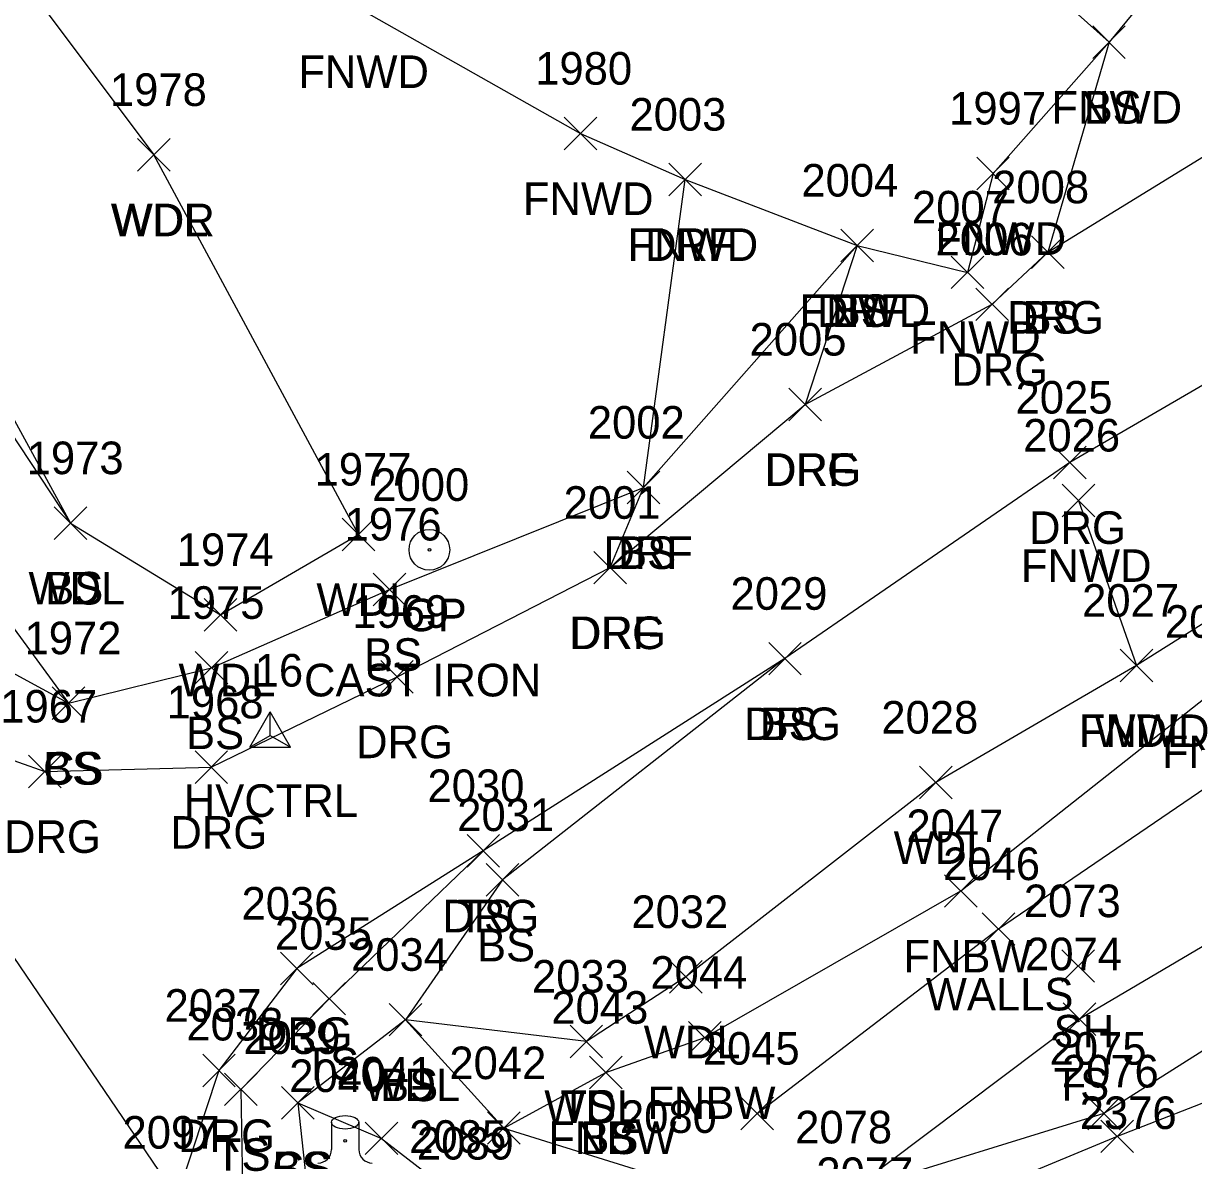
# Model space of a CAD drawing. Extents: x 1501299 to 1502485, y 381423 to 383765.
# Drawn here: x 1501597.6 to 1501669.5, y 383335.7 to 383405.5 of the extents above; entities that cross this region are included whole.
import ezdxf

# ---------------------------------------------------------------- set-up
doc = ezdxf.new("R2010")
doc.units = 0
for name, color, linetype in [('C_A', 7, 'Continuous'), ('C_I', 7, 'Continuous'), ('CPSM', 7, 'Continuous'), ('L_A', 7, 'Continuous'), ('L_I', 7, 'Continuous'), ('L_TIC', 7, 'Continuous'), ('LAWA', 7, 'Continuous'), ('LAWE', 7, 'Continuous'), ('LELB', 7, 'Continuous'), ('LFNC', 7, 'Continuous'), ('LTS', 7, 'Continuous'), ('LWS', 7, 'Continuous'), ('M_I', 7, 'Continuous'), ('P_I', 7, 'Continuous'), ('PET', 7, 'Continuous'), ('R_A', 7, 'Continuous'), ('R_C', 7, 'Continuous'), ('R_I', 7, 'Continuous'), ('R_TIC', 7, 'Continuous'), ('RDF', 7, 'Continuous'), ('RDG', 7, 'Continuous'), ('RGP', 7, 'Continuous')]:
    doc.layers.add(name, color=color, linetype=linetype)

msp = doc.modelspace()

# ---------------------------------------------------------------- linework, layer by layer
at = {"layer": 'CPSM'}
for p, q in [((1501611.52, 383361.059), (1501612.77, 383363.224)), ((1501614.02, 383361.059), (1501612.77, 383363.224)), ((1501612.771, 383361.781), (1501612.77, 383363.224)), ((1501611.52, 383361.059), (1501612.771, 383361.781)), ((1501612.771, 383361.781), (1501612.771, 383361.781)), ((1501612.771, 383361.781), (1501614.02, 383361.059)), ((1501611.52, 383361.059), (1501614.02, 383361.059))]:
    msp.add_line(p, q, dxfattribs=at)
at = {"layer": 'L_TIC'}
for points in [[(1501663.269, 383403.339), (1501665.269, 383405.339)], [(1501665.269, 383403.339), (1501663.269, 383405.339)], [(1501663.269, 383403.339), (1501665.269, 383405.339)], [(1501665.269, 383403.339), (1501663.269, 383405.339)], [(1501630.819, 383397.728), (1501632.819, 383399.728)], [(1501632.819, 383397.728), (1501630.819, 383399.728)], [(1501604.623, 383396.423), (1501606.623, 383398.423)], [(1501606.623, 383396.423), (1501604.623, 383398.423)], [(1501604.623, 383396.423), (1501606.623, 383398.423)], [(1501606.623, 383396.423), (1501604.623, 383398.423)], [(1501656.147, 383395.281), (1501658.147, 383397.281)], [(1501658.147, 383395.281), (1501656.147, 383397.281)], [(1501637.245, 383394.907), (1501639.245, 383396.907)], [(1501639.245, 383394.907), (1501637.245, 383396.907)], [(1501647.802, 383390.857), (1501649.802, 383392.857)], [(1501649.802, 383390.857), (1501647.802, 383392.857)], [(1501647.802, 383390.857), (1501649.802, 383392.857)], [(1501649.802, 383390.857), (1501647.802, 383392.857)], [(1501659.515, 383390.446), (1501661.515, 383392.446)], [(1501661.515, 383390.446), (1501659.515, 383392.446)], [(1501654.586, 383389.206), (1501656.586, 383391.206)], [(1501656.586, 383389.206), (1501654.586, 383391.206)], [(1501654.586, 383389.206), (1501656.586, 383391.206)], [(1501656.586, 383389.206), (1501654.586, 383391.206)], [(1501634.688, 383376), (1501636.688, 383378)], [(1501636.688, 383376), (1501634.688, 383378)], [(1501661.392, 383375.208), (1501663.392, 383377.208)], [(1501663.392, 383375.208), (1501661.392, 383377.208)], [(1501599.513, 383373.819), (1501601.513, 383375.819)], [(1501601.513, 383373.819), (1501599.513, 383375.819)], [(1501599.513, 383373.819), (1501601.513, 383375.819)], [(1501601.513, 383373.819), (1501599.513, 383375.819)], [(1501617.19, 383373.119), (1501619.19, 383375.119)], [(1501619.19, 383373.119), (1501617.19, 383375.119)], [(1501619.094, 383369.747), (1501621.094, 383371.747)], [(1501621.094, 383369.747), (1501619.094, 383371.747)], [(1501608.724, 383368.181), (1501610.724, 383370.181)], [(1501610.724, 383368.181), (1501608.724, 383370.181)], [(1501643.375, 383365.495), (1501645.375, 383367.495)], [(1501645.375, 383365.495), (1501643.375, 383367.495)], [(1501664.955, 383365.069), (1501666.955, 383367.069)], [(1501666.955, 383365.069), (1501664.955, 383367.069)], [(1501664.955, 383365.069), (1501666.955, 383367.069)], [(1501666.955, 383365.069), (1501664.955, 383367.069)], [(1501608.161, 383364.939), (1501610.161, 383366.939)], [(1501610.161, 383364.939), (1501608.161, 383366.939)], [(1501599.381, 383362.765), (1501601.381, 383364.765)], [(1501601.381, 383362.765), (1501599.381, 383364.765)], [(1501599.381, 383362.765), (1501601.381, 383364.765)], [(1501601.381, 383362.765), (1501599.381, 383364.765)], [(1501652.629, 383357.895), (1501654.629, 383359.895)], [(1501654.629, 383357.895), (1501652.629, 383359.895)], [(1501624.853, 383353.693), (1501626.853, 383355.693)], [(1501626.853, 383353.693), (1501624.853, 383355.693)], [(1501626.025, 383351.911), (1501628.025, 383353.911)], [(1501628.025, 383351.911), (1501626.025, 383353.911)], [(1501654.168, 383351.235), (1501656.168, 383353.235)], [(1501656.168, 383351.235), (1501654.168, 383353.235)], [(1501656.478, 383348.901), (1501658.478, 383350.901)], [(1501658.478, 383348.901), (1501656.478, 383350.901)], [(1501661.379, 383346.627), (1501663.379, 383348.627)], [(1501663.379, 383346.627), (1501661.379, 383348.627)], [(1501637.285, 383345.961), (1501639.285, 383347.961)], [(1501639.285, 383345.961), (1501637.285, 383347.961)], [(1501615.397, 383344.622), (1501617.397, 383346.622)], [(1501617.397, 383344.622), (1501615.397, 383346.622)], [(1501620.074, 383343.333), (1501622.074, 383345.333)], [(1501622.074, 383343.333), (1501620.074, 383345.333)], [(1501620.074, 383343.333), (1501622.074, 383345.333)], [(1501622.074, 383343.333), (1501620.074, 383345.333)], [(1501661.456, 383343.366), (1501663.456, 383345.366)], [(1501663.456, 383343.366), (1501661.456, 383345.366)], [(1501638.45, 383342.232), (1501640.45, 383344.232)], [(1501640.45, 383342.232), (1501638.45, 383344.232)], [(1501631.179, 383341.995), (1501633.179, 383343.995)], [(1501633.179, 383341.995), (1501631.179, 383343.995)], [(1501631.179, 383341.995), (1501633.179, 383343.995)], [(1501633.179, 383341.995), (1501631.179, 383343.995)], [(1501632.369, 383340.084), (1501634.369, 383342.084)], [(1501634.369, 383340.084), (1501632.369, 383342.084)], [(1501632.369, 383340.084), (1501634.369, 383342.084)], [(1501634.369, 383340.084), (1501632.369, 383342.084)], [(1501609.965, 383339.056), (1501611.965, 383341.056)], [(1501611.965, 383339.056), (1501609.965, 383341.056)], [(1501613.47, 383338.228), (1501615.47, 383340.228)], [(1501615.47, 383338.228), (1501613.47, 383340.228)], [(1501613.47, 383338.228), (1501615.47, 383340.228)], [(1501615.47, 383338.228), (1501613.47, 383340.228)], [(1501641.667, 383337.571), (1501643.667, 383339.571)], [(1501643.667, 383337.571), (1501641.667, 383339.571)], [(1501662.959, 383337.57), (1501664.959, 383339.57)], [(1501664.959, 383337.57), (1501662.959, 383339.57)], [(1501626.11, 383336.683), (1501628.11, 383338.683)], [(1501628.11, 383336.683), (1501626.11, 383338.683)], [(1501626.11, 383336.683), (1501628.11, 383338.683)], [(1501628.11, 383336.683), (1501626.11, 383338.683)], [(1501618.607, 383336.048), (1501620.607, 383338.048)], [(1501620.607, 383336.048), (1501618.607, 383338.048)], [(1501663.765, 383336.172), (1501665.765, 383338.172)], [(1501665.765, 383336.172), (1501663.765, 383338.172)]]:
    msp.add_lwpolyline(points, dxfattribs=at)
at = {"layer": 'LAWA'}
for points in [[(1501557.451, 383442.581), (1501575.149, 383424.231), (1501579.771, 383412.785), (1501600.513, 383374.819), (1501609.724, 383369.181), (1501618.19, 383374.119), (1501605.623, 383397.423)], [(1501557.451, 383442.581), (1501587.949, 383421), (1501605.623, 383397.423)], [(1501740.143, 383404.354), (1501720.425, 383392.48), (1501699.763, 383382.767), (1501677.935, 383373.609), (1501665.955, 383366.069), (1501653.629, 383358.895), (1501638.285, 383346.961), (1501632.179, 383342.995), (1501621.074, 383344.333), (1501627.11, 383337.683), (1501637.668, 383334.383)], [(1501750.74, 383385.706), (1501735.534, 383378.38), (1501721.306, 383366.598), (1501707.543, 383358.247), (1501693.275, 383349.984), (1501675.651, 383345.973), (1501663.959, 383338.57), (1501648.341, 383333.739), (1501637.668, 383334.383)]]:
    msp.add_lwpolyline(points, dxfattribs=at)
at = {"layer": 'LAWE'}
msp.add_lwpolyline([(1501751.7, 383384.782), (1501736.295, 383377.69), (1501721.533, 383363.11), (1501708.276, 383357.65), (1501696.432, 383349.133), (1501679.062, 383342.719), (1501664.765, 383337.172), (1501649.638, 383330.877), (1501644.08, 383325.549), (1501629.198, 383322.948), (1501623.396, 383326.029)], dxfattribs=at)
at = {"layer": 'LELB'}
for points in [[(1501358.62, 383732.982), (1501381.143, 383696.09), (1501398.686, 383667.715), (1501415.463, 383640.286), (1501435.304, 383603.989), (1501464.895, 383561.231), (1501485.321, 383525.1), (1501505.057, 383497.042), (1501522.935, 383468.146), (1501546.418, 383435.546), (1501564.602, 383407.152), (1501589.271, 383369.799), (1501600.381, 383363.765)], [(1501679.96, 383481.538), (1501668.05, 383454.246), (1501642.937, 383434.782), (1501647.006, 383419.763), (1501664.269, 383404.339), (1501660.515, 383391.446)], [(1501555.063, 383441.425), (1501575.01, 383413.454), (1501600.513, 383374.819)], [(1501550.473, 383437.331), (1501569.88, 383410.608), (1501593.858, 383372.658), (1501600.381, 383363.765), (1501609.161, 383365.939), (1501620.094, 383370.747), (1501635.688, 383377), (1501648.802, 383391.857)], [(1501644.375, 383366.495), (1501627.025, 383352.911), (1501621.074, 383344.333), (1501614.47, 383339.228), (1501619.607, 383337.048), (1501624.643, 383333.16)], [(1501704.558, 383362.823), (1501685.003, 383358.821), (1501674.317, 383351.353), (1501662.456, 383344.366), (1501648.341, 383333.739), (1501644.08, 383325.549)], [(1501625.853, 383354.693), (1501616.397, 383345.622), (1501610.965, 383340.056), (1501611.136, 383330.56), (1501615.516, 383325.125), (1501618.696, 383319.793)], [(1501627.11, 383337.683), (1501633.369, 383341.084)], [(1501614.47, 383339.228), (1501615.583, 383328.811), (1501620.097, 383323.129)]]:
    msp.add_lwpolyline(points, dxfattribs=at)
at = {"layer": 'LFNC'}
for points in [[(1501598.419, 383526.967), (1501583.574, 383507.223), (1501582.321, 383503.521), (1501551.423, 383461.963), (1501556.785, 383457.152), (1501570.079, 383443.827), (1501579.662, 383434.509), (1501590.927, 383422.471), (1501618.032, 383406.524), (1501631.819, 383398.728), (1501638.245, 383395.907), (1501648.802, 383391.857), (1501655.586, 383390.206)], [(1501703.45, 383452.334), (1501689.591, 383435.314), (1501672.608, 383414.438), (1501664.269, 383404.339), (1501657.147, 383396.281), (1501655.586, 383390.206)], [(1501662.392, 383376.208), (1501665.955, 383366.069)], [(1501633.369, 383341.084), (1501639.45, 383343.232), (1501655.168, 383352.235), (1501671.047, 383364.777), (1501683.649, 383372.385)]]:
    msp.add_lwpolyline(points, dxfattribs=at)
at = {"layer": 'LTS'}
for p, q in [((1501616.539, 383338.033), (1501616.539, 383336.366)), ((1501618.205, 383337.866), (1501618.205, 383338.033)), ((1501618.205, 383338.033), (1501618.205, 383336.366)), ((1501617.372, 383336.891), (1501617.372, 383336.891)), ((1501617.372, 383336.891), (1501617.372, 383336.891)), ((1501617.372, 383336.866), (1501617.372, 383336.866))]:
    msp.add_line(p, q, dxfattribs=at)
msp.add_circle((1501617.372, 383336.891), 0.0833, dxfattribs=at)
for centre, start, end in [((1501615.705, 383336.366), 270, 360), ((1501619.039, 383336.366), 180, 270)]:
    msp.add_arc(centre, 0.833, start, end, dxfattribs=at)
msp.add_ellipse((1501617.372, 383338.033), major_axis=(-0.833, 0), ratio=0.5, dxfattribs=at)
at = {"layer": 'LWS'}
msp.add_lwpolyline([(1501642.667, 383338.571), (1501657.478, 383349.901), (1501674.332, 383361.387), (1501682.14, 383365.291), (1501702.312, 383377.097)], dxfattribs=at)
at = {"layer": 'PET'}
msp.add_lwpolyline([(1501352.609, 383730.103), (1501376.04, 383692.663), (1501392.886, 383664.453), (1501409.551, 383637.048), (1501431.218, 383601.012), (1501459.286, 383556.771), (1501480.727, 383522.39), (1501500.041, 383493.106), (1501518.668, 383465.088), (1501539.809, 383433.288), (1501559.66, 383403.845), (1501585.888, 383364.546), (1501607.043, 383333.417), (1501616.485, 383318.818), (1501608.79, 383312.411), (1501601.645, 383306.284)], dxfattribs=at)
at = {"layer": 'R_TIC'}
for points in [[(1501637.245, 383394.907), (1501639.245, 383396.907)], [(1501639.245, 383394.907), (1501637.245, 383396.907)], [(1501647.802, 383390.857), (1501649.802, 383392.857)], [(1501649.802, 383390.857), (1501647.802, 383392.857)], [(1501659.515, 383390.446), (1501661.515, 383392.446)], [(1501661.515, 383390.446), (1501659.515, 383392.446)], [(1501656.095, 383387.246), (1501658.095, 383389.246)], [(1501658.095, 383387.246), (1501656.095, 383389.246)], [(1501644.617, 383381.098), (1501646.617, 383383.098)], [(1501646.617, 383381.098), (1501644.617, 383383.098)], [(1501644.617, 383381.098), (1501646.617, 383383.098)], [(1501646.617, 383381.098), (1501644.617, 383383.098)], [(1501660.87, 383377.539), (1501662.87, 383379.539)], [(1501662.87, 383377.539), (1501660.87, 383379.539)], [(1501634.688, 383376), (1501636.688, 383378)], [(1501636.688, 383376), (1501634.688, 383378)], [(1501632.637, 383371.08), (1501634.637, 383373.08)], [(1501634.637, 383371.08), (1501632.637, 383373.08)], [(1501632.637, 383371.08), (1501634.637, 383373.08)], [(1501634.637, 383371.08), (1501632.637, 383373.08)], [(1501643.375, 383365.495), (1501645.375, 383367.495)], [(1501645.375, 383365.495), (1501643.375, 383367.495)], [(1501619.557, 383364.386), (1501621.557, 383366.386)], [(1501621.557, 383364.386), (1501619.557, 383366.386)], [(1501597.939, 383358.572), (1501599.939, 383360.572)], [(1501599.939, 383358.572), (1501597.939, 383360.572)], [(1501608.156, 383358.828), (1501610.156, 383360.828)], [(1501610.156, 383358.828), (1501608.156, 383360.828)], [(1501624.853, 383353.693), (1501626.853, 383355.693)], [(1501626.853, 383353.693), (1501624.853, 383355.693)], [(1501613.404, 383346.477), (1501615.404, 383348.477)], [(1501615.404, 383346.477), (1501613.404, 383348.477)], [(1501608.625, 383340.209), (1501610.625, 383342.209)], [(1501610.625, 383340.209), (1501608.625, 383342.209)]]:
    msp.add_lwpolyline(points, dxfattribs=at)
at = {"layer": 'RDF'}
for points in [[(1501633.637, 383372.08), (1501635.688, 383377), (1501638.245, 383395.907)], [(1501648.802, 383391.857), (1501645.617, 383382.098)]]:
    msp.add_lwpolyline(points, dxfattribs=at)
at = {"layer": 'RDG'}
for points in [[(1501585.888, 383364.546), (1501592.449, 383361.853), (1501598.939, 383359.572), (1501609.156, 383359.828), (1501620.557, 383365.386), (1501633.637, 383372.08), (1501645.617, 383382.098), (1501657.095, 383388.246), (1501660.515, 383391.446), (1501681.22, 383404.169), (1501705.776, 383415.265), (1501726.712, 383424.327)], [(1501733.479, 383413.356), (1501709.016, 383404.067), (1501690.807, 383395.363), (1501661.87, 383378.539), (1501644.375, 383366.495), (1501625.853, 383354.693), (1501614.404, 383347.477), (1501609.625, 383341.209), (1501607.043, 383333.417)]]:
    msp.add_lwpolyline(points, dxfattribs=at)
at = {"layer": 'RGP'}
msp.add_line((1501622.543, 383373.177), (1501622.543, 383373.177), dxfattribs=at)
for radius in [1.25, 0.0833]:
    msp.add_circle((1501622.543, 383373.177), radius, dxfattribs=at)

# ---------------------------------------------------------------- texts
at = {"layer": 'C_A'}
msp.add_text('HVCTRL', height=2, dxfattribs=at).set_placement((1501607.464, 383356.781))
at = {"layer": 'C_I'}
msp.add_text('16', height=2, dxfattribs=at).set_placement((1501611.818, 383364.781))
at = {"layer": 'L_A'}
for s, p in [('FNWD', (1501614.496, 383401.524)), ('FNWD', (1501660.734, 383399.339)), ('BS', (1501662.71, 383399.339)), ('FNWD', (1501628.284, 383393.728)), ('WDR', (1501602.985, 383392.423)), ('WDL', (1501603.04, 383392.423)), ('FNWD', (1501634.709, 383390.907)), ('FNWD', (1501653.611, 383391.281)), ('FNWD', (1501645.266, 383386.857)), ('BS', (1501647.243, 383386.857)), ('BS', (1501658.956, 383386.446)), ('FNWD', (1501652.051, 383385.206)), ('FNWD', (1501652.051, 383385.206)), ('BS', (1501634.129, 383372)), ('FNWD', (1501658.857, 383371.208)), ('WDL', (1501597.93, 383369.819)), ('BS', (1501598.954, 383369.819)), ('WDL', (1501615.607, 383369.119)), ('BS', (1501618.535, 383365.747)), ('WDL', (1501607.141, 383364.181)), ('BS', (1501642.816, 383361.495)), ('BS', (1501607.602, 383360.939)), ('FNWD', (1501662.42, 383361.069)), ('WDL', (1501663.372, 383361.069)), ('FNBW', (1501667.519, 383359.777)), ('CS', (1501598.822, 383358.765)), ('BS', (1501598.822, 383358.765)), ('WDL', (1501651.046, 383353.895)), ('TS', (1501624.263, 383349.693)), ('BS', (1501625.466, 383347.911)), ('FNBW', (1501651.641, 383347.235)), ('WALLS', (1501653.021, 383344.901)), ('SH', (1501660.867, 383342.627)), ('WDL', (1501635.702, 383341.961)), ('TS', (1501614.807, 383340.622)), ('WDL', (1501618.492, 383339.333)), ('BS', (1501619.515, 383339.333)), ('TS', (1501660.865, 383339.366)), ('WDL', (1501629.597, 383337.995)), ('TS', (1501630.589, 383337.995)), ('FNBW', (1501635.922, 383338.232)), ('FNBW', (1501629.842, 383336.084)), ('BS', (1501631.81, 383336.084)), ('TS', (1501609.374, 383335.056)), ('CS', (1501612.911, 383334.228)), ('BS', (1501612.911, 383334.228))]:
    msp.add_text(s, height=2, dxfattribs=at).set_placement(p)
at = {"layer": 'L_I'}
for s, p in [('1980', (1501629.04, 383401.728)), ('1978', (1501602.93, 383400.423)), ('1978', (1501602.93, 383400.423)), ('2003', (1501634.827, 383398.907)), ('1997', (1501654.454, 383399.281)), ('2004', (1501645.384, 383394.857)), ('2004', (1501645.384, 383394.857)), ('2008', (1501657.097, 383394.446)), ('2007', (1501652.169, 383393.206)), ('2007', (1501652.169, 383393.206)), ('2002', (1501632.271, 383380)), ('2026', (1501658.999, 383379.208)), ('1973', (1501597.82, 383377.819)), ('1973', (1501597.82, 383377.819)), ('1977', (1501615.497, 383377.119)), ('1976', (1501617.346, 383373.747)), ('1974', (1501607.031, 383372.181)), ('2029', (1501641.029, 383369.495)), ('1975', (1501606.468, 383368.939)), ('2027', (1501662.617, 383369.069)), ('2027', (1501662.617, 383369.069)), ('2049', (1501667.7, 383367.777)), ('1972', (1501597.688, 383366.765)), ('1972', (1501597.688, 383366.765)), ('2028', (1501650.29, 383361.895)), ('2030', (1501622.428, 383357.693)), ('2031', (1501624.254, 383355.911)), ('2047', (1501651.83, 383355.235)), ('2046', (1501654.084, 383352.901)), ('2073', (1501659.04, 383350.627)), ('2032', (1501634.946, 383349.961)), ('2035', (1501613.059, 383348.622)), ('2034', (1501617.736, 383347.333)), ('2034', (1501617.736, 383347.333)), ('2074', (1501659.117, 383347.366)), ('2033', (1501628.841, 383345.995)), ('2033', (1501628.841, 383345.995)), ('2044', (1501636.111, 383346.232)), ('2043', (1501630.031, 383344.084)), ('2043', (1501630.031, 383344.084)), ('2038', (1501607.626, 383343.056)), ('2039', (1501611.123, 383342.228)), ('2039', (1501611.123, 383342.228)), ('2045', (1501639.329, 383341.571)), ('2075', (1501660.621, 383341.57)), ('2042', (1501623.771, 383340.683)), ('2042', (1501623.771, 383340.683)), ('2040', (1501613.942, 383339.893)), ('2041', (1501616.836, 383340.048)), ('2076', (1501661.372, 383340.172)), ('2080', (1501634.243, 383337.383)), ('2080', (1501634.243, 383337.383)), ('2080', (1501634.243, 383337.383)), ('2376', (1501662.47, 383337.622)), ('2078', (1501645.002, 383336.739)), ('2078', (1501645.002, 383336.739)), ('2085', (1501621.305, 383336.16)), ('2077', (1501646.299, 383333.877))]:
    msp.add_text(s, height=2, dxfattribs=at).set_placement(p)
at = {"layer": 'M_I'}
msp.add_text('2089', height=2, dxfattribs=at).set_placement((1501621.777, 383335.748))
at = {"layer": 'P_I'}
msp.add_text('2097', height=2, dxfattribs=at).set_placement((1501603.705, 383336.417))
at = {"layer": 'R_A'}
for s, p in [('DRF', (1501635.78, 383390.907)), ('DRF', (1501646.337, 383386.857)), ('DRG', (1501658.003, 383386.446)), ('DRG', (1501654.584, 383383.246)), ('DRG', (1501643.105, 383377.098)), ('DRF', (1501643.152, 383377.098)), ('DRG', (1501659.358, 383373.539)), ('DRF', (1501633.223, 383372)), ('GP', (1501620.976, 383368.177)), ('DRG', (1501631.125, 383367.08)), ('DRF', (1501631.172, 383367.08)), ('DRG', (1501641.863, 383361.495)), ('DRG', (1501618.046, 383360.386)), ('DRG', (1501596.427, 383354.572)), ('DRG', (1501606.644, 383354.828)), ('DRG', (1501623.342, 383349.693)), ('DRG', (1501611.892, 383342.477)), ('DRG', (1501607.113, 383336.209))]:
    msp.add_text(s, height=2, dxfattribs=at).set_placement(p)
at = {"layer": 'R_C'}
msp.add_text('CAST IRON', height=2, dxfattribs=at).set_placement((1501614.85, 383364.177))
at = {"layer": 'R_I'}
for s, p in [('2003', (1501634.827, 383398.907)), ('2004', (1501645.384, 383394.857)), ('2008', (1501657.097, 383394.446)), ('2006', (1501653.623, 383391.246)), ('2005', (1501642.2, 383385.098)), ('2005', (1501642.2, 383385.098)), ('2025', (1501658.531, 383381.539)), ('2002', (1501632.271, 383380)), ('2000', (1501619.039, 383376.177)), ('2001', (1501630.786, 383375.08)), ('2001', (1501630.786, 383375.08)), ('2029', (1501641.029, 383369.495)), ('1969', (1501617.81, 383368.386)), ('1968', (1501606.416, 383362.828)), ('1967', (1501596.199, 383362.572)), ('2030', (1501622.428, 383357.693)), ('2036', (1501611.011, 383350.477)), ('2037', (1501606.286, 383344.209)), ('2097', (1501603.705, 383336.417))]:
    msp.add_text(s, height=2, dxfattribs=at).set_placement(p)

doc.saveas('drawing.dxf')
